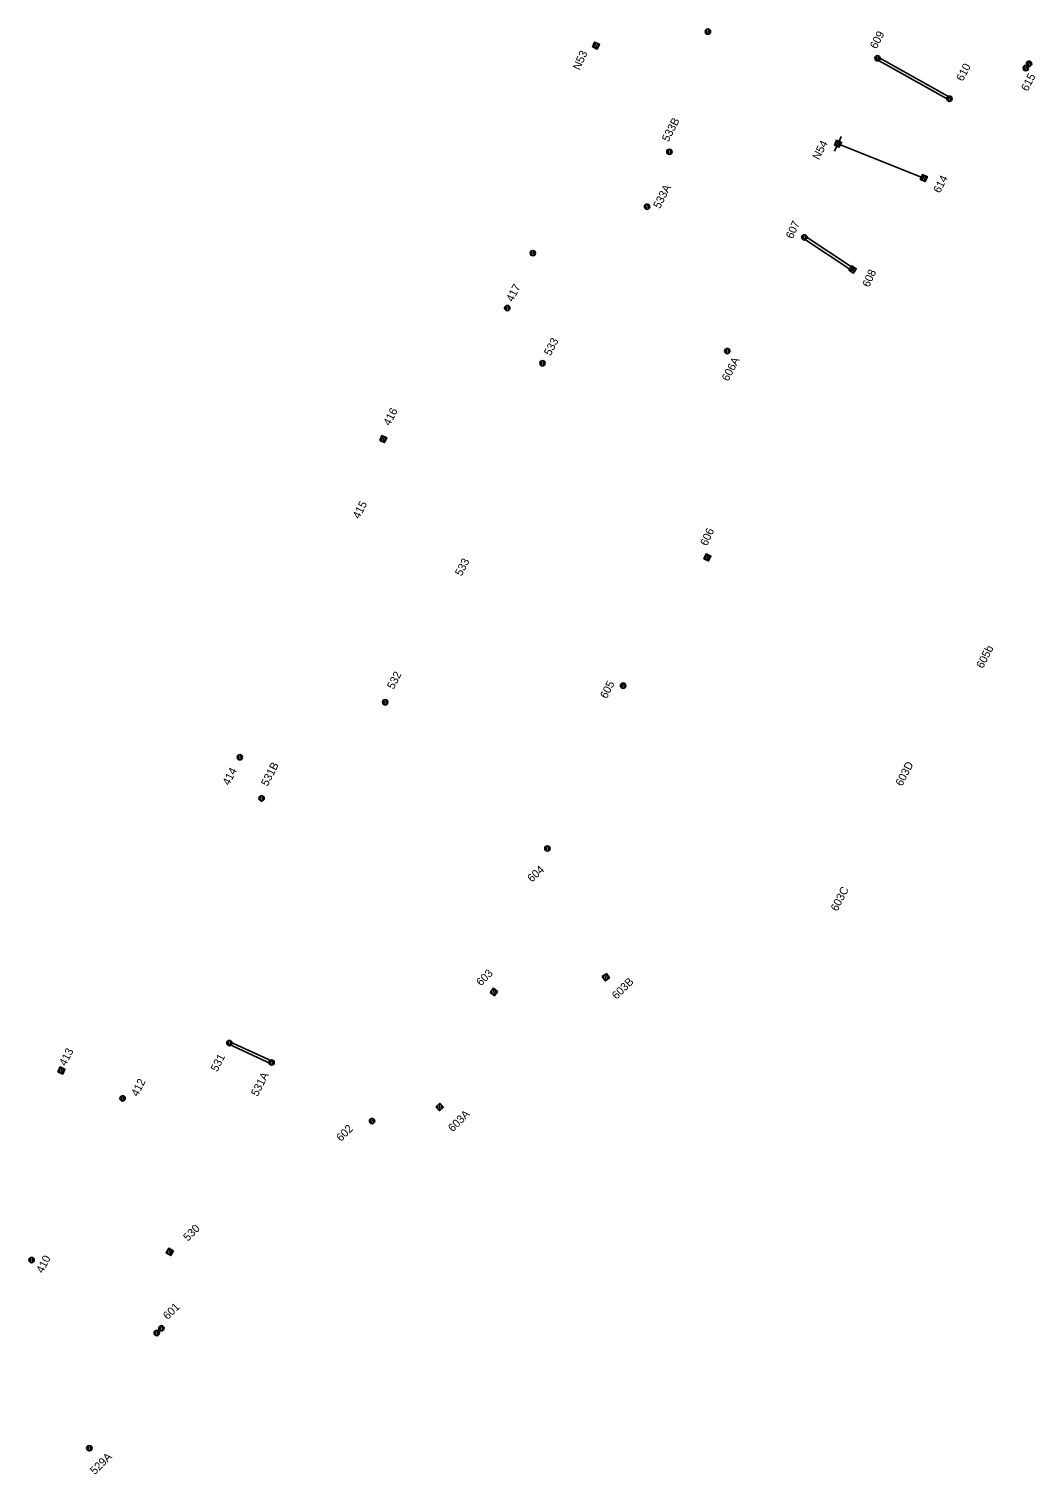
# Model space of a CAD drawing. Extents: x -595867 to -593796, y -1159595 to -1157495.
# Drawn here: x -594926.7 to -594738.2, y -1159111.2 to -1158840.4 of the extents above; entities that cross this region are included whole.
import ezdxf

# ---------------------------------------------------------------- set-up
doc = ezdxf.new("R2010")
doc.units = 0
for name, color, linetype in [('BVK_kanalizace_jednotna_nova', 7, 'Continuous'), ('DKM18', 7, 'Continuous'), ('DKM19', 7, 'Continuous'), ('SO31_06_54_1-protlak', 7, 'Continuous'), ('Vrstva 2', 7, 'Continuous')]:
    doc.layers.add(name, color=color, linetype=linetype)

# ---------------------------------------------------------------- blocks, each defined once
blk = doc.blocks.new('C661_2')
at = {"layer": 'SO31_06_54_1-protlak'}
for p, q in [((-0.005, 0.0003), (-0.0003, 0.005)), ((-0.005, -0.005), (0.005, 0.005)), ((0.0003, -0.005), (0.005, -0.0003))]:
    blk.add_line(p, q, dxfattribs=at)
blk.add_lwpolyline([(-0.005, 0.005), (0.005, 0.005), (0.005, -0.005), (-0.005, -0.005)], close=True, dxfattribs=at)
blk.add_lwpolyline([(-0.005, 0.005), (0.005, 0.005), (0.005, -0.005), (-0.005, -0.005), (-0.005, 0.005)], dxfattribs=at)
blk = doc.blocks.new('C661_1')
at = {"layer": 'SO31_06_54_1-protlak'}
for p, q in [((-0.005, 0.0003), (-0.0003, 0.005)), ((-0.005, -0.005), (0.005, 0.005)), ((0.0003, -0.005), (0.005, -0.0003))]:
    blk.add_line(p, q, dxfattribs=at)
blk.add_lwpolyline([(-0.005, 0.005), (0.005, 0.005), (0.005, -0.005), (-0.005, -0.005)], close=True, dxfattribs=at)
blk.add_lwpolyline([(-0.005, 0.005), (0.005, 0.005), (0.005, -0.005), (-0.005, -0.005), (-0.005, 0.005)], dxfattribs=at)
blk = doc.blocks.new('C666')
at = {"layer": 'SO31_06_54_1-protlak'}
for p, q in [((-0.005, 0.0001), (-0.0001, 0.005)), ((-0.0048, -0.005), (0.005, 0.0048)), ((0.0049, 0), (0.015, 0)), ((-0.005, 0), (-0.015, 0)), ((0.0005, -0.005), (0.005, -0.0005))]:
    blk.add_line(p, q, dxfattribs=at)
blk.add_lwpolyline([(-0.005, 0.005), (0.005, 0.005), (0.005, -0.005), (-0.005, -0.005)], close=True, dxfattribs=at)
blk.add_lwpolyline([(-0.005, 0.005), (0.005, 0.005), (0.005, -0.005), (-0.005, -0.005), (-0.005, 0.005)], dxfattribs=at)

msp = doc.modelspace()

# ---------------------------------------------------------------- linework, layer by layer
at = {"layer": 'BVK_kanalizace_jednotna_nova'}
for p, q in [((-594799.61, -1158841.33), (-594799.77, -1158840.43)), ((-594799.24, -1158841.28), (-594799.41, -1158840.36)), ((-594767.78, -1158846.34), (-594768.05, -1158845.47)), ((-594767.42, -1158846.24), (-594767.69, -1158845.35)), ((-594739.98, -1158848.19), (-594740.25, -1158847.32)), ((-594739.62, -1158848.09), (-594739.89, -1158847.21)), ((-594739.38, -1158847.37), (-594739.65, -1158846.5)), ((-594739.02, -1158847.27), (-594739.29, -1158846.39)), ((-594754.29, -1158853.93), (-594754.56, -1158853.06)), ((-594753.93, -1158853.83), (-594754.2, -1158852.95)), ((-594806.82, -1158863.86), (-594806.98, -1158862.96)), ((-594806.45, -1158863.8), (-594806.61, -1158862.89)), ((-594811.02, -1158874.16), (-594811.18, -1158873.26)), ((-594810.65, -1158874.1), (-594810.81, -1158873.19)), ((-594781.54, -1158879.9), (-594781.7, -1158879)), ((-594781.17, -1158879.84), (-594781.33, -1158878.93)), ((-594832.41, -1158882.85), (-594832.57, -1158881.95)), ((-594832.04, -1158882.79), (-594832.2, -1158881.88)), ((-594837.2, -1158893.14), (-594837.36, -1158892.24)), ((-594836.83, -1158893.08), (-594836.99, -1158892.17)), ((-594795.97, -1158901.21), (-594796.13, -1158900.31)), ((-594795.6, -1158901.16), (-594795.76, -1158900.24)), ((-594830.59, -1158903.48), (-594830.75, -1158902.58)), ((-594830.22, -1158903.43), (-594830.38, -1158902.51)), ((-594815.49, -1158963.91), (-594815.65, -1158963.01)), ((-594815.12, -1158963.85), (-594815.29, -1158962.94)), ((-594860.07, -1158967.01), (-594860.23, -1158966.11)), ((-594859.7, -1158966.95), (-594859.86, -1158966.04)), ((-594887.29, -1158977.32), (-594887.45, -1158976.42)), ((-594886.92, -1158977.26), (-594887.08, -1158976.35)), ((-594883.21, -1158985.04), (-594883.37, -1158984.14)), ((-594882.84, -1158984.98), (-594883, -1158984.07)), ((-594829.68, -1158994.42), (-594829.84, -1158993.52)), ((-594829.31, -1158994.37), (-594829.47, -1158993.45)), ((-594889.26, -1159030.89), (-594889.42, -1159029.99)), ((-594888.89, -1159030.83), (-594889.06, -1159029.92)), ((-594881.34, -1159034.53), (-594881.5, -1159033.63)), ((-594880.97, -1159034.48), (-594881.13, -1159033.56)), ((-594909.26, -1159041.26), (-594909.42, -1159040.36)), ((-594908.89, -1159041.2), (-594909.06, -1159040.29)), ((-594862.53, -1159045.51), (-594862.69, -1159044.61)), ((-594862.16, -1159045.45), (-594862.32, -1159044.54)), ((-594926.31, -1159071.56), (-594926.47, -1159070.66)), ((-594925.94, -1159071.51), (-594926.1, -1159070.59)), ((-594902.86, -1159085.24), (-594903.02, -1159084.34)), ((-594902.49, -1159085.19), (-594902.66, -1159084.27)), ((-594901.99, -1159084.33), (-594902.15, -1159083.43)), ((-594901.62, -1159084.27), (-594901.79, -1159083.36)), ((-594915.49, -1159106.81), (-594915.65, -1159105.91)), ((-594915.12, -1159106.76), (-594915.29, -1159105.84))]:
    msp.add_line(p, q, dxfattribs=at)
for points in [[(-594754.36, -1158853.66), (-594767.85, -1158846.07)], [(-594754.12, -1158853.22), (-594767.61, -1158845.63)], [(-594775.13, -1158861.87), (-594759.04, -1158868.3)], [(-594772.52, -1158885.63), (-594781.57, -1158879.63)], [(-594772.24, -1158885.21), (-594781.29, -1158879.21)], [(-594881.33, -1159034.28), (-594889.25, -1159030.64)], [(-594881.12, -1159033.82), (-594889.05, -1159030.18)]]:
    msp.add_lwpolyline(points, dxfattribs=at)
for centre in [(-594799.5, -1158840.85), (-594799.5, -1158840.85), (-594767.73, -1158845.85), (-594767.73, -1158845.85), (-594739.93, -1158847.7), (-594739.93, -1158847.7), (-594739.33, -1158846.88), (-594739.33, -1158846.88), (-594754.24, -1158853.44), (-594754.24, -1158853.44), (-594806.71, -1158863.38), (-594806.71, -1158863.38), (-594810.9, -1158873.68), (-594810.9, -1158873.68), (-594781.43, -1158879.42), (-594781.43, -1158879.42), (-594832.3, -1158882.37), (-594832.3, -1158882.37), (-594837.09, -1158892.66), (-594837.09, -1158892.66), (-594795.86, -1158900.73), (-594795.86, -1158900.73), (-594830.48, -1158903), (-594830.48, -1158903), (-594815.38, -1158963.43), (-594815.38, -1158963.43), (-594859.96, -1158966.53), (-594859.96, -1158966.53), (-594887.18, -1158976.84), (-594887.18, -1158976.84), (-594883.1, -1158984.56), (-594883.1, -1158984.56), (-594829.57, -1158993.94), (-594829.57, -1158993.94), (-594889.15, -1159030.41), (-594889.15, -1159030.41), (-594881.23, -1159034.05), (-594881.23, -1159034.05), (-594909.15, -1159040.78), (-594909.15, -1159040.78), (-594862.42, -1159045.03), (-594862.42, -1159045.03), (-594926.2, -1159071.08), (-594926.2, -1159071.08), (-594902.75, -1159084.76), (-594902.75, -1159084.76), (-594901.88, -1159083.85), (-594901.88, -1159083.85), (-594915.38, -1159106.33), (-594915.38, -1159106.33)]:
    msp.add_circle(centre, 0.5, dxfattribs=at)
at = {"layer": 'Vrstva 2'}
msp.add_line((-594772.38, -1158885.42), (-594772.38, -1158885.42), dxfattribs=at)
msp.add_lwpolyline([(-594773.07, -1158885.55), (-594772.25, -1158886.11), (-594771.69, -1158885.29), (-594772.51, -1158884.73), (-594773.07, -1158885.55), (-594772.67, -1158885.58), (-594772.33, -1158885.09), (-594772.09, -1158885.26), (-594772.42, -1158885.75)], dxfattribs=at)

# ---------------------------------------------------------------- block references
for name, p, xscale, yscale, rotation in [('C661_2', (-594820.48, -1158843.48), 99.99957555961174, 99.99957555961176, 65.30990745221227), ('C666', (-594775.13, -1158861.87), 99.99957555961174, 99.99957555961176, 65.30990745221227), ('C661_2', (-594759.04, -1158868.3), 99.99957555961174, 99.99957555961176, 65.30990745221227), ('C661_2', (-594860.32, -1158917.22), 99.99957555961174, 99.99957555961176, 65.30990745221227), ('C661_2', (-594799.6, -1158939.4), 99.99957555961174, 99.99957555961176, 65.30990745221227), ('C661_2', (-594818.62, -1159018.06), 99.99968210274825, 99.99968210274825, 35.32047560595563), ('C661_2', (-594839.59, -1159020.84), 99.99971999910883, 99.99971999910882, 52.859293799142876), ('C661_2', (-594920.61, -1159035.55), 99.99967137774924, 99.99967137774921, 65.39359517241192), ('C661_2', (-594849.75, -1159042.39), 99.99947022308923, 99.99947022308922, 43.900419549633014), ('C661_1', (-594900.32, -1159069.55), 99.99966837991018, 99.99966837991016, -119.65811099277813)]:
    msp.add_blockref(name, p, dxfattribs=dict(at, xscale=xscale, yscale=yscale, rotation=rotation))

# ---------------------------------------------------------------- texts
at = {"layer": 'BVK_kanalizace_jednotna_nova'}
for s, rotation, p in [('609', 62.6209, (-594767.91, -1158844.22)), ('N53', 65.5984, (-594823.53, -1158848.19)), ('610', 62.6209, (-594751.74, -1158850.29)), ('615', 62.6209, (-594739.6, -1158852.16)), ('N54', 62.6209, (-594778.68, -1158865.01)), ('614', 62.6209, (-594756.05, -1158871.25)), ('607', 65.5984, (-594783.62, -1158879.81)), ('608', 65.5984, (-594769.3, -1158888.89)), ('606', 65.5984, (-594799.66, -1158937.36))]:
    msp.add_text(s, height=1.5, rotation=rotation, dxfattribs=at).set_placement(p)
at = {"layer": 'DKM18'}
for s, rotation, p in [('533B', 62.6209, (-594806.89, -1158861.64)), ('533A', 62.6209, (-594808.51, -1158874.16)), ('417', 62.6209, (-594836.07, -1158891.63)), ('533', 62.6209, (-594828.97, -1158901.72)), ('606A', 62.6209, (-594795.67, -1158906.5)), ('416', 62.6209, (-594859.09, -1158914.84)), ('415', 62.6209, (-594864.82, -1158932.29)), ('533', 62.6209, (-594845.64, -1158943.02)), ('605b', 62.6209, (-594747.98, -1158960.32)), ('532', 62.6209, (-594858.37, -1158964.23)), ('605', 62.6209, (-594818.47, -1158965.99)), ('414', 62.6209, (-594889.21, -1158982.25)), ('531B', 62.6209, (-594881.99, -1158982.41)), ('603D', 62.6209, (-594763.13, -1158982.39)), ('604', 42.6209, (-594832.49, -1159000.35)), ('603C', 62.6209, (-594775.27, -1159005.84)), ('603', 44.8189, (-594842.02, -1159019.81))]:
    msp.add_text(s, height=1.5, rotation=rotation, dxfattribs=at).set_placement(p)
at = {"layer": 'DKM19'}
for s, rotation, p in [('603B', 44.8189, (-594816.6, -1159022.33)), ('413', 63, (-594919.81, -1159034.82)), ('531', 63, (-594891.41, -1159035.89)), ('531A', 63, (-594883.85, -1159040.52)), ('412', 63, (-594906.31, -1159040.54)), ('603A', 44.8189, (-594847.29, -1159047.15)), ('602', 44.8189, (-594868.24, -1159048.95)), ('530', 44.8189, (-594896.91, -1159067.64)), ('410', 63, (-594924.09, -1159073.65)), ('601', 44.8189, (-594900.7, -1159082.35)), ('529A', 44.8189, (-594914.35, -1159111.38))]:
    msp.add_text(s, height=1.5, rotation=rotation, dxfattribs=at).set_placement(p)

doc.saveas('drawing.dxf')
